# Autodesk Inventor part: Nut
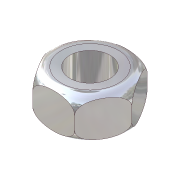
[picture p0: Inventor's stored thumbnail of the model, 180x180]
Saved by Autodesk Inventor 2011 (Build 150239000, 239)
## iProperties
Shininess: 77.0
Length Units: 11269
Angle Units: 11279
Time Units: 11290
Mass Units: 11283
Length Display Precision: 3
Angle Display Precision: 2
Created: 2002-02
Part Number: Nut
Document SubType Name: Modeling
Designer: ***
Density: 1 g/cm^3
Density: 0.0
Volumn: 0.0
Area: 0.0
PropertySet Name: Model Information
Control State: 0
Master: False
Checked Out: False
Author: ***
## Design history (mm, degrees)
sketch "Sketch1"
  geometry: C1 r 12.5 at (0, 0)
  constraints: 1 centre point
  dimensions: "d0" = 25 diameter of C1
extrude "Extrusion1" new body sketch "Sketch1" stored distance "d1" = 12; taper "d2" = 0 deg
fillet "Fillet1" dims "d3" = 4
sketch "Sketch2"
  geometry: L1 (12.5, 0)-(6.25, -10.825); L2 (6.25, -10.825)-(-6.25, -10.825); L3 (-6.25, -10.825)-(-12.5, 0); L4 (-12.5, 0)-(-6.25, 10.825); L5 (-6.25, 10.825)-(6.25, 10.825); L6 (6.25, 10.825)-(12.5, 0); C1 r 8.5 at (0, 0) reference; 1 further point
  constraints: 12 end point, 1 coincident, 11 other
extrude "Extrusion2" sketch "Sketch2" stored distance "d4" = 12; taper "d5" = 0 deg
sketch "Sketch3"
  geometry: C1 r 8.5 at (0, 0) reference
hole "Hole1" sketch "Sketch3" at (0, 0) diameter "d6" = 12; stored, may be unused: countersink angle "d10" = 82 deg, drill point angle "d12" = 118 deg; dims "d7" = 6, "d8" = 4, "d9" = 2, "d11" = 8
body "Solid1"
